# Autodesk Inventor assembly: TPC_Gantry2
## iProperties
Shininess: 64.0
Length Units: 11272
Angle Units: 11279
Time Units: 11290
Mass Units: 11286
Length Display Precision: 3
Angle Display Precision: 2
Compacted: True
Part Number: TPC_Gantry2
Document SubType Name: Assembly
Created: 2004-08
Designer: Lori
Manufacturer: Standard
Standards Organization: Custom
Density: 0.0
Volumn: 0.0
Area: 0.0
PropertySet Name: Model Information
Control State: 0
Master: False
Checked Out: False
Author: Lori
